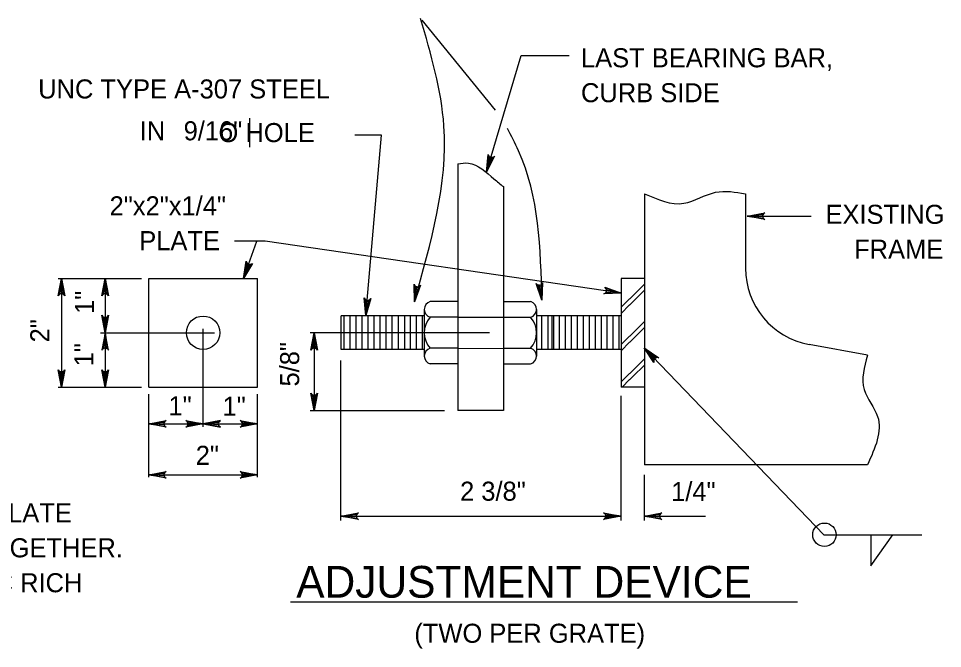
# Model space of a CAD drawing. Extents: x -0.3 to 6.9, y -6.5 to 3.5.
# Drawn here: x 3.655 to 6.564, y -3.239 to -1.255 of the extents above; entities that cross this region are included whole.
import ezdxf

# ---------------------------------------------------------------- set-up
doc = ezdxf.new("R2010")
doc.units = 0
for name, color, linetype in [('DETL-DIMS', 7, 'Continuous'), ('DETL-LINE', 7, 'Continuous'), ('DETL-NOTE', 7, 'Continuous'), ('DETL-PATT', 7, 'Continuous'), ('DETL-TITL', 7, 'Continuous')]:
    doc.layers.add(name, color=color, linetype=linetype)

msp = doc.modelspace()

# ---------------------------------------------------------------- linework, layer by layer
at = {"layer": 'DETL-DIMS'}
for p, q in [((5.157, -1.5433), (4.9261, -1.2596)), ((5.1284, -1.7384), (5.2377, -1.3717)), ((5.2377, -1.3717), (5.3889, -1.3717)), ((4.7979, -1.6224), (4.7147, -1.6224)), ((4.7494, -2.1902), (4.7979, -1.6224)), ((5.9499, -1.8771), (6.151, -1.8771)), ((4.4325, -1.9558), (4.3354, -1.9558)), ((4.3637, -2.0739), (4.4059, -1.9558)), ((5.5539, -2.1194), (4.4325, -1.9558)), ((3.7807, -2.0731), (4.0426, -2.0731)), ((3.7908, -2.0731), (3.7908, -2.4156)), ((3.9281, -2.0731), (3.9281, -2.4156)), ((4.2367, -2.5412), (4.2367, -2.2323)), ((3.9138, -2.2444), (4.2721, -2.2444)), ((5.1384, -2.2444), (4.5738, -2.2444)), ((4.5863, -2.2444), (4.5863, -2.4898)), ((5.6255, -2.2914), (6.1906, -2.8806)), ((4.6705, -2.8361), (4.6705, -2.3322)), ((3.7807, -2.4156), (4.0426, -2.4156)), ((4.0654, -2.6988), (4.0654, -2.4381)), ((4.408, -2.6988), (4.408, -2.4381)), ((5.5524, -2.8361), (5.5524, -2.4435)), ((4.5738, -2.4898), (4.9963, -2.4898)), ((4.0654, -2.5312), (4.408, -2.5312)), ((4.0654, -2.6917), (4.408, -2.6917)), ((5.6258, -2.8361), (5.6258, -2.6917)), ((4.6705, -2.8219), (5.5524, -2.8219)), ((5.6258, -2.8219), (5.8182, -2.8219)), ((6.1906, -2.8806), (6.499, -2.8806)), ((6.3387, -2.8806), (6.3387, -2.9781)), ((6.3387, -2.9781), (6.4079, -2.8806))]:
    msp.add_line(p, q, dxfattribs=at)
for points in [[(5.1284, -1.7384), (5.1342, -1.6829), (5.1358, -1.6878), (5.1387, -1.6909), (5.142, -1.6926), (5.1457, -1.693), (5.1499, -1.692), (5.1539, -1.6888), (5.1284, -1.7384), (5.1499, -1.692), (5.1457, -1.693), (5.1284, -1.7384), (5.142, -1.6926), (5.1387, -1.6909), (5.1284, -1.7384), (5.1358, -1.6878)], [(5.9499, -1.8771), (6.0048, -1.8669), (6.0005, -1.8698), (5.9984, -1.8735), (5.9977, -1.8771), (5.9984, -1.8808), (6.0005, -1.8845), (6.0048, -1.8874), (5.9499, -1.8771), (6.0005, -1.8845), (5.9984, -1.8808), (5.9499, -1.8771), (5.9977, -1.8771), (5.9984, -1.8735), (5.9499, -1.8771), (6.0005, -1.8698)], [(4.3637, -2.0739), (4.3724, -2.0189), (4.3738, -2.0238), (4.3765, -2.0271), (4.3798, -2.0289), (4.3834, -2.0296), (4.3876, -2.0288), (4.3918, -2.0258), (4.3637, -2.0739), (4.3876, -2.0288), (4.3834, -2.0296), (4.3637, -2.0739), (4.3798, -2.0289), (4.3765, -2.0271), (4.3637, -2.0739), (4.3738, -2.0238)], [(3.7908, -2.0731), (3.801, -2.1279), (3.7981, -2.1237), (3.7944, -2.1215), (3.7908, -2.1209), (3.7871, -2.1215), (3.7834, -2.1237), (3.7805, -2.1279), (3.7908, -2.0731), (3.7834, -2.1237), (3.7871, -2.1215), (3.7908, -2.0731), (3.7908, -2.1209), (3.7944, -2.1215), (3.7908, -2.0731), (3.7981, -2.1237)], [(3.7908, -2.0731), (3.801, -2.1279), (3.7981, -2.1237), (3.7944, -2.1215), (3.7908, -2.1209), (3.7871, -2.1215), (3.7834, -2.1237), (3.7805, -2.1279), (3.7908, -2.0731), (3.7834, -2.1237), (3.7871, -2.1215), (3.7908, -2.0731), (3.7908, -2.1209), (3.7944, -2.1215), (3.7908, -2.0731), (3.7981, -2.1237)], [(3.9281, -2.0731), (3.9384, -2.1279), (3.9355, -2.1237), (3.9318, -2.1215), (3.9281, -2.1209), (3.9245, -2.1215), (3.9208, -2.1237), (3.9179, -2.1279), (3.9281, -2.0731), (3.9208, -2.1237), (3.9245, -2.1215), (3.9281, -2.0731), (3.9281, -2.1209), (3.9318, -2.1215), (3.9281, -2.0731), (3.9355, -2.1237)], [(4.9016, -2.1467), (4.9006, -2.0909), (4.9028, -2.0956), (4.906, -2.0983), (4.9096, -2.0996), (4.9133, -2.0996), (4.9173, -2.098), (4.9209, -2.0943), (4.9016, -2.1467), (4.9173, -2.098), (4.9133, -2.0996), (4.9016, -2.1467), (4.9096, -2.0996), (4.906, -2.0983), (4.9016, -2.1467), (4.9028, -2.0956)], [(4.9016, -2.1467), (4.9006, -2.0909), (4.9028, -2.0956), (4.906, -2.0983), (4.9096, -2.0996), (4.9133, -2.0996), (4.9173, -2.098), (4.9209, -2.0943), (4.9016, -2.1467), (4.9173, -2.098), (4.9133, -2.0996), (4.9016, -2.1467), (4.9096, -2.0996), (4.906, -2.0983), (4.9016, -2.1467), (4.9028, -2.0956)], [(5.3033, -2.1418), (5.2847, -2.0892), (5.2883, -2.0929), (5.2922, -2.0945), (5.296, -2.0946), (5.2995, -2.0934), (5.3028, -2.0907), (5.305, -2.086), (5.3033, -2.1418), (5.3028, -2.0907), (5.2995, -2.0934), (5.3033, -2.1418), (5.296, -2.0946), (5.2922, -2.0945), (5.3033, -2.1418), (5.2883, -2.0929)], [(5.3033, -2.1418), (5.2847, -2.0892), (5.2883, -2.0929), (5.2922, -2.0945), (5.296, -2.0946), (5.2995, -2.0934), (5.3028, -2.0907), (5.305, -2.086), (5.3033, -2.1418), (5.3028, -2.0907), (5.2995, -2.0934), (5.3033, -2.1418), (5.296, -2.0946), (5.2922, -2.0945), (5.3033, -2.1418), (5.2883, -2.0929)], [(5.5539, -2.1194), (5.4981, -2.1217), (5.5027, -2.1194), (5.5054, -2.1161), (5.5066, -2.1125), (5.5065, -2.1088), (5.5048, -2.1048), (5.5011, -2.1013), (5.5539, -2.1194), (5.5048, -2.1048), (5.5065, -2.1088), (5.5539, -2.1194), (5.5066, -2.1125), (5.5054, -2.1161), (5.5539, -2.1194), (5.5027, -2.1194)], [(4.7494, -2.1902), (4.7438, -2.1347), (4.7464, -2.1392), (4.7498, -2.1417), (4.7534, -2.1426), (4.7572, -2.1423), (4.761, -2.1404), (4.7643, -2.1365), (4.7494, -2.1902), (4.761, -2.1404), (4.7572, -2.1423), (4.7494, -2.1902), (4.7534, -2.1426), (4.7498, -2.1417), (4.7494, -2.1902), (4.7464, -2.1392)], [(3.9281, -2.2444), (3.9179, -2.1895), (3.9208, -2.1938), (3.9245, -2.1959), (3.9281, -2.1966), (3.9318, -2.1959), (3.9355, -2.1938), (3.9384, -2.1895), (3.9281, -2.2444), (3.9355, -2.1938), (3.9318, -2.1959), (3.9281, -2.2444), (3.9281, -2.1966), (3.9245, -2.1959), (3.9281, -2.2444), (3.9208, -2.1938)], [(3.9281, -2.2444), (3.9179, -2.2992), (3.9208, -2.295), (3.9245, -2.2928), (3.9281, -2.2921), (3.9318, -2.2928), (3.9355, -2.295), (3.9384, -2.2992), (3.9281, -2.2444), (3.9355, -2.295), (3.9318, -2.2928), (3.9281, -2.2444), (3.9281, -2.2921), (3.9245, -2.2928), (3.9281, -2.2444), (3.9208, -2.295)], [(4.5863, -2.2444), (4.5966, -2.2992), (4.5936, -2.295), (4.5899, -2.2928), (4.5863, -2.2921), (4.5826, -2.2928), (4.5789, -2.295), (4.576, -2.2992), (4.5863, -2.2444), (4.5789, -2.295), (4.5826, -2.2928), (4.5863, -2.2444), (4.5863, -2.2921), (4.5899, -2.2928), (4.5863, -2.2444), (4.5936, -2.295)], [(5.6255, -2.2914), (5.6708, -2.3238), (5.6658, -2.3228), (5.6616, -2.3238), (5.6585, -2.3259), (5.6563, -2.3289), (5.6552, -2.333), (5.656, -2.3381), (5.6255, -2.2914), (5.6552, -2.333), (5.6563, -2.3289), (5.6255, -2.2914), (5.6585, -2.3259), (5.6616, -2.3238), (5.6255, -2.2914), (5.6658, -2.3228)], [(3.7908, -2.4156), (3.7805, -2.3608), (3.7834, -2.365), (3.7871, -2.3672), (3.7908, -2.3679), (3.7944, -2.3672), (3.7981, -2.365), (3.801, -2.3608), (3.7908, -2.4156), (3.7981, -2.365), (3.7944, -2.3672), (3.7908, -2.4156), (3.7908, -2.3679), (3.7871, -2.3672), (3.7908, -2.4156), (3.7834, -2.365)], [(3.7908, -2.4156), (3.7805, -2.3608), (3.7834, -2.365), (3.7871, -2.3672), (3.7908, -2.3679), (3.7944, -2.3672), (3.7981, -2.365), (3.801, -2.3608), (3.7908, -2.4156), (3.7981, -2.365), (3.7944, -2.3672), (3.7908, -2.4156), (3.7908, -2.3679), (3.7871, -2.3672), (3.7908, -2.4156), (3.7834, -2.365)], [(3.9281, -2.4156), (3.9179, -2.3608), (3.9208, -2.365), (3.9245, -2.3672), (3.9281, -2.3679), (3.9318, -2.3672), (3.9355, -2.365), (3.9384, -2.3608), (3.9281, -2.4156), (3.9355, -2.365), (3.9318, -2.3672), (3.9281, -2.4156), (3.9281, -2.3679), (3.9245, -2.3672), (3.9281, -2.4156), (3.9208, -2.365)], [(4.5863, -2.4898), (4.576, -2.435), (4.5789, -2.4392), (4.5826, -2.4414), (4.5863, -2.442), (4.5899, -2.4414), (4.5936, -2.4392), (4.5966, -2.435), (4.5863, -2.4898), (4.5936, -2.4392), (4.5899, -2.4414), (4.5863, -2.4898), (4.5863, -2.442), (4.5826, -2.4414), (4.5863, -2.4898), (4.5789, -2.4392)], [(4.0654, -2.5312), (4.1202, -2.5209), (4.116, -2.5238), (4.1138, -2.5275), (4.1132, -2.5312), (4.1138, -2.5349), (4.116, -2.5386), (4.1202, -2.5415), (4.0654, -2.5312), (4.116, -2.5386), (4.1138, -2.5349), (4.0654, -2.5312), (4.1132, -2.5312), (4.1138, -2.5275), (4.0654, -2.5312), (4.116, -2.5238)], [(4.0654, -2.5312), (4.1202, -2.5209), (4.116, -2.5238), (4.1138, -2.5275), (4.1132, -2.5312), (4.1138, -2.5349), (4.116, -2.5386), (4.1202, -2.5415), (4.0654, -2.5312), (4.116, -2.5386), (4.1138, -2.5349), (4.0654, -2.5312), (4.1132, -2.5312), (4.1138, -2.5275), (4.0654, -2.5312), (4.116, -2.5238)], [(4.2367, -2.5312), (4.1819, -2.5415), (4.1861, -2.5386), (4.1883, -2.5349), (4.1889, -2.5312), (4.1883, -2.5275), (4.1861, -2.5238), (4.1819, -2.5209), (4.2367, -2.5312), (4.1861, -2.5238), (4.1883, -2.5275), (4.2367, -2.5312), (4.1889, -2.5312), (4.1883, -2.5349), (4.2367, -2.5312), (4.1861, -2.5386)], [(4.2367, -2.5312), (4.2915, -2.5415), (4.2873, -2.5386), (4.2851, -2.5349), (4.2845, -2.5312), (4.2851, -2.5275), (4.2873, -2.5238), (4.2915, -2.5209), (4.2367, -2.5312), (4.2873, -2.5238), (4.2851, -2.5275), (4.2367, -2.5312), (4.2845, -2.5312), (4.2851, -2.5349), (4.2367, -2.5312), (4.2873, -2.5386)], [(4.408, -2.5312), (4.3532, -2.5415), (4.3574, -2.5386), (4.3596, -2.5349), (4.3602, -2.5312), (4.3596, -2.5275), (4.3574, -2.5238), (4.3532, -2.5209), (4.408, -2.5312), (4.3574, -2.5238), (4.3596, -2.5275), (4.408, -2.5312), (4.3602, -2.5312), (4.3596, -2.5349), (4.408, -2.5312), (4.3574, -2.5386)], [(4.408, -2.5312), (4.3532, -2.5415), (4.3574, -2.5386), (4.3596, -2.5349), (4.3602, -2.5312), (4.3596, -2.5275), (4.3574, -2.5238), (4.3532, -2.5209), (4.408, -2.5312), (4.3574, -2.5238), (4.3596, -2.5275), (4.408, -2.5312), (4.3602, -2.5312), (4.3596, -2.5349), (4.408, -2.5312), (4.3574, -2.5386)], [(4.0654, -2.6917), (4.1202, -2.6814), (4.116, -2.6843), (4.1138, -2.688), (4.1132, -2.6917), (4.1138, -2.6954), (4.116, -2.699), (4.1202, -2.702), (4.0654, -2.6917), (4.116, -2.699), (4.1138, -2.6954), (4.0654, -2.6917), (4.1132, -2.6917), (4.1138, -2.688), (4.0654, -2.6917), (4.116, -2.6843)], [(4.0654, -2.6917), (4.1202, -2.6814), (4.116, -2.6843), (4.1138, -2.688), (4.1132, -2.6917), (4.1138, -2.6954), (4.116, -2.699), (4.1202, -2.702), (4.0654, -2.6917), (4.116, -2.699), (4.1138, -2.6954), (4.0654, -2.6917), (4.1132, -2.6917), (4.1138, -2.688), (4.0654, -2.6917), (4.116, -2.6843)], [(4.408, -2.6917), (4.3532, -2.702), (4.3574, -2.699), (4.3596, -2.6954), (4.3602, -2.6917), (4.3596, -2.688), (4.3574, -2.6843), (4.3532, -2.6814), (4.408, -2.6917), (4.3574, -2.6843), (4.3596, -2.688), (4.408, -2.6917), (4.3602, -2.6917), (4.3596, -2.6954), (4.408, -2.6917), (4.3574, -2.699)], [(4.6705, -2.8219), (4.7254, -2.8116), (4.7212, -2.8145), (4.719, -2.8182), (4.7183, -2.8219), (4.719, -2.8255), (4.7212, -2.8292), (4.7254, -2.8321), (4.6705, -2.8219), (4.7212, -2.8292), (4.719, -2.8255), (4.6705, -2.8219), (4.7183, -2.8219), (4.719, -2.8182), (4.6705, -2.8219), (4.7212, -2.8145)], [(4.6705, -2.8219), (4.7254, -2.8116), (4.7212, -2.8145), (4.719, -2.8182), (4.7183, -2.8219), (4.719, -2.8255), (4.7212, -2.8292), (4.7254, -2.8321), (4.6705, -2.8219), (4.7212, -2.8292), (4.719, -2.8255), (4.6705, -2.8219), (4.7183, -2.8219), (4.719, -2.8182), (4.6705, -2.8219), (4.7212, -2.8145)], [(5.5524, -2.8219), (5.4976, -2.8321), (5.5018, -2.8292), (5.504, -2.8255), (5.5046, -2.8219), (5.504, -2.8182), (5.5018, -2.8145), (5.4976, -2.8116), (5.5524, -2.8219), (5.5018, -2.8145), (5.504, -2.8182), (5.5524, -2.8219), (5.5046, -2.8219), (5.504, -2.8255), (5.5524, -2.8219), (5.5018, -2.8292)], [(5.5524, -2.8219), (5.4976, -2.8321), (5.5018, -2.8292), (5.504, -2.8255), (5.5046, -2.8219), (5.504, -2.8182), (5.5018, -2.8145), (5.4976, -2.8116), (5.5524, -2.8219), (5.5018, -2.8145), (5.504, -2.8182), (5.5524, -2.8219), (5.5046, -2.8219), (5.504, -2.8255), (5.5524, -2.8219), (5.5018, -2.8292)], [(5.6258, -2.8219), (5.6807, -2.8116), (5.6764, -2.8145), (5.6743, -2.8182), (5.6736, -2.8219), (5.6743, -2.8255), (5.6764, -2.8292), (5.6807, -2.8321), (5.6258, -2.8219), (5.6764, -2.8292), (5.6743, -2.8255), (5.6258, -2.8219), (5.6736, -2.8219), (5.6743, -2.8182), (5.6258, -2.8219), (5.6764, -2.8145)]]:
    msp.add_lwpolyline(points, dxfattribs=at)
msp.add_circle((6.1927, -2.8806), 0.0369, dxfattribs=at)
for points in [[(4.9016, -2.1467), (4.9947, -1.5929), (4.9212, -1.2547)], [(5.3033, -2.1418), (5.2299, -1.6713), (5.1944, -1.6009)]]:
    msp.add_spline(points, degree=3, dxfattribs=at)
at = {"layer": 'DETL-LINE'}
for p, q in [((5.0383, -1.7123), (5.0383, -2.4898)), ((5.1822, -1.7842), (5.1822, -2.4898)), ((5.6258, -1.8067), (5.6258, -2.0731)), ((5.944, -1.8067), (5.944, -2.0407)), ((4.0654, -2.4156), (4.0654, -2.0731)), ((4.0654, -2.0731), (4.408, -2.0731)), ((4.408, -2.4156), (4.408, -2.0731)), ((5.5524, -2.0731), (5.5524, -2.4156)), ((5.6258, -2.0731), (5.5524, -2.0731)), ((5.6258, -2.0731), (5.6258, -2.4156)), ((5.0378, -2.1465), (4.9514, -2.1465)), ((5.1814, -2.1465), (5.2678, -2.1465)), ((4.9329, -2.1709), (4.9328, -2.3178)), ((5.2863, -2.1709), (5.2864, -2.3178)), ((4.6705, -2.1916), (4.6705, -2.2971)), ((4.9326, -2.1916), (4.6715, -2.1916)), ((4.9326, -2.1916), (4.9326, -2.2971)), ((5.0383, -2.1954), (4.9514, -2.1954)), ((5.0383, -2.1954), (5.1822, -2.1954)), ((5.181, -2.1954), (5.2678, -2.1954)), ((5.5524, -2.1916), (5.2866, -2.1916)), ((5.2866, -2.1916), (5.2866, -2.2971)), ((4.9326, -2.2971), (4.6715, -2.2971)), ((5.0383, -2.2933), (4.9514, -2.2933)), ((5.0383, -2.294), (5.1822, -2.2934)), ((5.181, -2.2933), (5.2678, -2.2933)), ((5.5524, -2.2971), (5.2866, -2.2971)), ((6.3283, -2.3154), (6.1442, -2.2813)), ((5.0378, -2.3422), (4.9514, -2.3422)), ((5.1814, -2.3422), (5.2678, -2.3422)), ((4.0654, -2.4156), (4.408, -2.4156)), ((5.6258, -2.4156), (5.5524, -2.4156)), ((5.6258, -2.4156), (5.6258, -2.6604)), ((5.1822, -2.4898), (5.0383, -2.4898)), ((6.3283, -2.6604), (5.6258, -2.6604))]:
    msp.add_line(p, q, dxfattribs=at)
msp.add_circle((4.2367, -2.2444), 0.0527, dxfattribs=at)
for centre, radius, start, end in [((6.1887, -2.0407), 0.2447, 180, 259.5325), ((4.9584, -2.1709), 0.0254, 105.829, 254.171), ((5.2609, -2.1709), 0.0254, 285.829, 74.171), ((5.0056, -2.2444), 0.073, 137.925, 222.075), ((5.2136, -2.2444), 0.073, 317.925, 42.075), ((4.9582, -2.3178), 0.0254, 105.5103, 254.4897), ((5.261, -2.3178), 0.0254, 285.5103, 74.4897)]:
    msp.add_arc(centre, radius, start, end, dxfattribs=at)
for points in [[(5.0383, -1.7123), (5.0718, -1.71), (5.1523, -1.7599), (5.1822, -1.7842)], [(5.6258, -1.8067), (5.7504, -1.8366), (5.8501, -1.8021), (5.944, -1.8067)], [(6.3283, -2.3154), (6.3178, -2.4235), (6.36, -2.5079), (6.3283, -2.6604)]]:
    msp.add_spline(points, degree=3, dxfattribs=at)
at = {"layer": 'DETL-NOTE'}
msp.add_line((4.3826, -1.5682), (4.3826, -1.6601), dxfattribs=at)
at = {"layer": 'DETL-PATT'}
for p, q in [((5.5797, -2.1372), (5.6258, -2.0911)), ((5.5895, -2.147), (5.6258, -2.1107)), ((5.5524, -2.1641), (5.5695, -2.147)), ((5.5695, -2.147), (5.5793, -2.1372)), ((5.5895, -2.147), (5.5793, -2.1573)), ((5.5524, -2.1837), (5.5793, -2.1568)), ((4.68, -2.1916), (4.68, -2.2971)), ((4.6988, -2.1916), (4.6988, -2.2971)), ((4.7176, -2.1916), (4.7176, -2.2971)), ((4.7364, -2.1916), (4.7364, -2.2971)), ((4.7553, -2.1916), (4.7553, -2.2971)), ((4.7741, -2.1916), (4.7741, -2.2971)), ((4.7931, -2.1908), (4.7931, -2.2962)), ((4.8117, -2.1916), (4.8117, -2.2971)), ((4.8305, -2.1916), (4.8305, -2.2971)), ((4.8512, -2.1899), (4.8512, -2.2953)), ((4.8703, -2.1916), (4.8703, -2.2971)), ((4.888, -2.1916), (4.888, -2.2971)), ((4.9076, -2.1916), (4.9076, -2.2971)), ((4.9262, -2.1916), (4.9262, -2.2971)), ((5.3018, -2.1916), (5.3018, -2.2971)), ((5.3214, -2.1916), (5.3214, -2.2971)), ((5.3344, -2.1916), (5.3344, -2.2971)), ((5.3401, -2.1916), (5.3401, -2.2971)), ((5.3574, -2.1916), (5.3574, -2.2971)), ((5.3764, -2.1916), (5.3764, -2.2971)), ((5.3952, -2.1916), (5.3952, -2.2971)), ((5.414, -2.1916), (5.414, -2.2971)), ((5.4328, -2.1916), (5.4328, -2.2971)), ((5.4517, -2.1916), (5.4517, -2.2971)), ((5.4705, -2.1916), (5.4705, -2.2971)), ((5.4893, -2.1916), (5.4893, -2.2971)), ((5.5081, -2.1916), (5.5081, -2.2971)), ((5.527, -2.1916), (5.527, -2.2971)), ((5.5458, -2.1916), (5.5458, -2.2971)), ((5.5797, -2.2549), (5.6258, -2.2088)), ((5.6258, -2.2284), (5.5797, -2.2745)), ((5.5524, -2.2818), (5.5793, -2.2549)), ((5.5524, -2.3014), (5.5793, -2.2745)), ((5.5797, -2.3725), (5.6258, -2.3264)), ((5.5895, -2.3823), (5.6258, -2.346)), ((5.5524, -2.3994), (5.5695, -2.3823)), ((5.5695, -2.3823), (5.5793, -2.3725)), ((5.5895, -2.3823), (5.5793, -2.3926)), ((5.5558, -2.4156), (5.5793, -2.3921))]:
    msp.add_line(p, q, dxfattribs=at)
at = {"layer": 'DETL-TITL'}
msp.add_line((4.5113, -3.0914), (6.1082, -3.0914), dxfattribs=at)

# ---------------------------------------------------------------- texts
at = {"layer": 'DETL-NOTE'}
for s, p in [('LAST BEARING BAR,', (5.4262, -1.4084)), (' UNC TYPE A-307 STEEL', (3.6951, -1.5066)), ('CURB SIDE', (5.4262, -1.5184)), ('IN', (4.037, -1.6384)), ('9/16"', (4.1753, -1.6384)), ('  O HOLE  ', (4.2405, -1.644)), ('2"x2"x1/4"', (3.9422, -1.8747)), ('EXISTING', (6.1959, -1.9014)), ('PLATE', (4.0356, -1.9844)), ('FRAME', (6.2861, -2.0114)), ('1"', (4.1276, -2.5042)), ('1"', (4.2978, -2.506)), ('2"', (4.2134, -2.6604)), ('2 3/8"', (5.0455, -2.7734)), ('1/4"', (5.71, -2.7746)), ('GALV. THE STUD & PLATE', (2.8114, -2.8417)), ('  SEPARATELY.WELD TOGETHER.', (2.6689, -2.9517)), ('TOUCH UP WITH ZINC RICH', (2.7824, -3.0617)), ('(TWO PER GRATE)', (4.9016, -3.2208))]:
    msp.add_text(s, height=0.06, dxfattribs=at).set_placement(p)
for s, p in [('1"', (3.893, -2.1852)), ('2"', (3.7525, -2.2748)), ('1"', (3.8911, -2.3503)), ('5/8"', (4.539, -2.4137))]:
    msp.add_text(s, height=0.06, rotation=90, dxfattribs=at).set_placement(p)
at = {"layer": 'DETL-TITL'}
msp.add_text('ADJUSTMENT DEVICE', height=0.1, dxfattribs=at).set_placement((4.5298, -3.0788))

doc.saveas('drawing.dxf')
